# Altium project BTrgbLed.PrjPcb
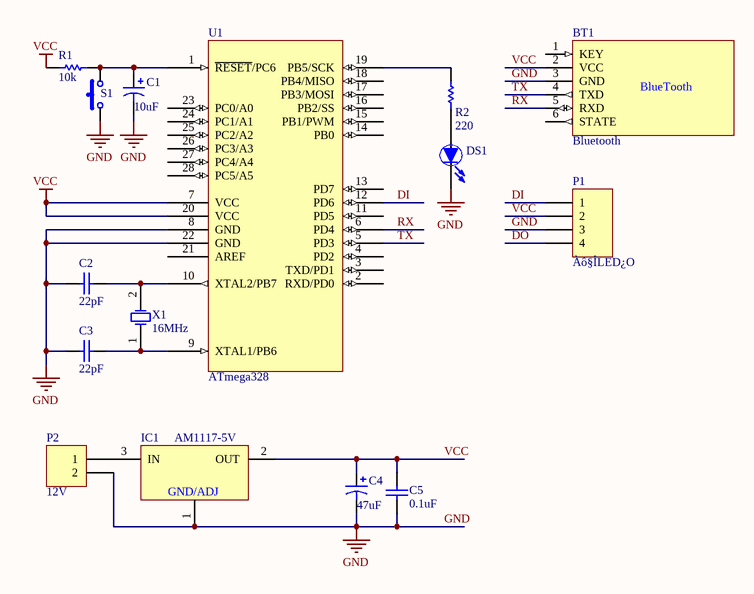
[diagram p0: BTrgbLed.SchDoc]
1 sheet, 15 parts. Net scope: global (net labels, ports and power ports of the same name join across sheets).
Board file: BTrgbLed.PcbDoc

## Sheet BTrgbLed.SchDoc
size A4

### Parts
BT1  Bluetooth  [Bluetooth]
C1  value 10uF  [RB7.6-15]  (hidden comment: 47uF)
C2  22pF  [C200]
C3  22pF  [C200]
C4  47uF  [RB7.6-15]
C5  0.1uF  [C200]
DS1  TX-LED  [LED-3mm_G]  (value not drawn)
IC1  AM1117-5V  [SOT-223]
P1  Àô§ÎLED¿O  [HDR1X4]
P2  12V  [HDR1X2]
R1  10k  [AXIAL-0.3]
R2  220  [AXIAL-0.3]
S1  SW-PB  [TACK6]  (value not drawn)
U1  ATmega328  [DIP-28]
X1  16MHz  [XTAL4-8]

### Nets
GND: BT1.3(GND) C1.2 C2.1 C3.1 C4.2 C5.1 DS1.2(K) IC1.1(ADJ/GND) P1.3 P2.2 S1.1 U1.8(GND) U1.22(GND)
VCC: BT1.2(VCC) C4.1 C5.2 IC1.2(OUT) P1.2 R1.1 U1.7(VCC) U1.20(VCC)
DI: P1.1 U1.12(PD6)
DO: P1.4
RX: BT1.5(RXD) U1.6(PD4)
TX: BT1.4(TXD) U1.5(PD3)
NetC1_1: C1.1 R1.2 S1.2 U1.1(~{RESET}/PC6)
NetC2_2: C2.2 U1.10(XTAL2/PB7) X1.2(OSC2)
NetC3_2: C3.2 U1.9(XTAL1/PB6) X1.1(OSC1)
NetDS1_1: DS1.1(A) R2.1
NetIC1_3: IC1.3(IN) P2.1
NetR2_2: R2.2 U1.19(PB5/SCK)

Not connected (* = marked no-connect by the designer): BT1 1(KEY) 6(STATE); U1 2(RXD/PD0) 3(TXD/PD1) 4(PD2) 11(PD5) 13(PD7) 14(PB0) 15(PB1/PWM) 16(PB2/SS) 17(PB3/MOSI) 18(PB4/MISO) 21(AREF) 23(PC0/A0) 24(PC1/A1) 25(PC2/A2) 26(PC3/A3) 27(PC4/A4) 28(PC5/A5)

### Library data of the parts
C1 C4 = Cap Pol1: Polarized Capacitor (Radial)
C2 C3 C5 = Cap: Capacitor
DS1 = LED: Typical INFRARED GaAs LED
IC1 = AM1117
P1 = Header 4: Header, 4-Pin
P2 = Header 2: Header, 2-Pin
R1 R2 = Res: Resistor
S1 = SW-PB: Switch
U1 = ATmega328: Arduino
X1 = XTAL: Crystal Oscillator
